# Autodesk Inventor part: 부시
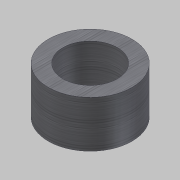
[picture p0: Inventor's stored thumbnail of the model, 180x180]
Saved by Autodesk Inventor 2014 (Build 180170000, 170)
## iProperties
Company: 한국ATC센터
Created: 2014-10
Part Number: 부시
Document SubType Name: Modeling
Designer: 한국ATC센터
Density: 7.86 g/cm^3
Material: 강, 연강
Mass: 157.788 g
Surface Area: 70.2617 cm^2
Volume: 20.0748 cm^3
Appearance: 금속-강(기계 가공_02)
Author: KYOUNG IL JANG
Revision Number: 1
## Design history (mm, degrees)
sketch "스케치1"
  geometry: C1 r 21.5 at (0, 0) reference; C2 r 31 at (0, 0) reference; C3 r 14 at (0, 0) reference; 1 further point
  node "참조1"
  node "참조2"
node "작업 평면1"
extrude "돌출1" new body sketch "스케치1" stored distance "d0" = 10; taper "d1" = 0 deg
node "솔리드1"
